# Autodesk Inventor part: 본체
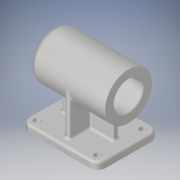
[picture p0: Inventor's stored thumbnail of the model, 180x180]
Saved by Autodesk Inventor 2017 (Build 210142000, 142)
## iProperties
Part Number: 본체
Material: 알루미늄 6061
Document SubType Name: Modeling
Designer: 7-1
Density: 2.7 g/cm^3
Appearance: 알루미늄 - 평지
Mass: 1024.73 g
Surface Area: 758.632 cm^2
Volume: 379.531 cm^3
Author: 7-1
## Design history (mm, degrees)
sketch "스케치1"
  geometry: L1 (0, 0)-(-112, 0); L2 (0, 21)-(0, 34); L3 (-112, 0)-(-112, 24); L4 (-102, 34)-(0, 34); L5 (-106, 0)-(-106, 10.5); L6 (-106, 10.5)-(-103, 10.5); L7 (-103, 10.5)-(-103, 15.7); L8 (-102.7, 16)-(-99, 16); L9 (-99, 16)-(-99, 17.2); L10 (-98.7, 17.5)-(-81, 17.5); L11 (-69, 24)-(-15, 24); L12 (-15, 24)-(-15, 21); L13 (-69, 24)-(-69, 21); L14 (-69, 21)-(-80.7, 21); L15 (-81, 20.7)-(-81, 17.5); L16 (-15, 21)-(0, 21); L17 (0, 34)-(0, 0); L18 (-112, 0)-(-106, 0); L19 (0, 34)-(0, 21); A1 r 0.3 centre (-102.7, 15.7) between (-102.7, 16) and (-103, 15.7); A2 r 0.3 centre (-98.7, 17.2) between (-98.7, 17.5) and (-99, 17.2); A3 r 0.3 centre (-80.7, 20.7) between (-80.7, 21) and (-81, 20.7); A4 r 10 centre (-102, 24) between (-102, 34) and (-112, 24)
  constraints: 38 end point, 13 perpendicular, 8 point on circle, 8 tangent, 4 centre point, 3 vertical, 2 equal radius, 1 collinear, 1 horizontal, 1 point on line
  dimensions: "d1" = 112 distance between parallel lines of L2 L3; "d2" = 21 diameter of L6 L1; "d3" = 32 diameter of L8 L1; "d4" = 35 diameter of L10 L1; "d5" = 42 diameter of L14 L1; "d6" = 48 diameter of L11 L1; "d7" = 68 diameter of L4 L1; "d8" = 42 diameter of L16 L1; "d9" = 15 distance between parallel lines of L2 L12; "d10" = 54 distance between parallel lines of L12 L13; "d11" = 12 distance between parallel lines of L13 L15; "d12" = 18 distance between parallel lines of L15 L9; "d13" = 3 distance between parallel lines of L7 L5; "d14" = 4 distance between parallel lines of L9 L7; "d15" = 0.3 radius of A1; "d16" = 10 radius of A4
revolve "회전1" sketch "스케치1" stored, may be unused: angle "d17" = 90 deg
node "스케치2"
node "작업 평면1"
sketch "스케치3"
  geometry: L1 (100, -45)-(12, -45); L2 (0, -33)-(0, 33); L3 (12, 45)-(100, 45); L4 (112, 33)-(112, -33); A1 r 12 centre (100, -33) between (100, -45) and (112, -33); A2 r 12 centre (100, 33) between (112, 33) and (100, 45); A3 r 12 centre (12, 33) between (12, 45) and (0, 33); A4 r 12 centre (12, -33) between (0, -33) and (12, -45); 4 further points
  constraints: 8 end point, 8 point on circle, 8 tangent, 6 point on line, 4 centre point, 3 equal radius, 2 parallel, 1 horizontal, 1 perpendicular
  dimensions: "d19" = 112 distance of point (0, 45) point (112, 45); "d20" = 90 distance of point (0, -45) point (0, 45); "d21" = 0 distance from line of point (0, 0) L2; "d22" = 45 distance from line of point (0, 0) L3; "d23" = 12 radius of A1
extrude "돌출1" join sketch "스케치3" distance "d24" = 10; taper "d25" = 0 deg
sketch "스케치4"
  geometry: A1 r 12 centre (-100, 33) between (-100, 45) and (-112, 33) reference; A2 r 12 centre (-100, -33) between (-112, -33) and (-100, -45) reference; A3 r 12 centre (-12, -33) between (-12, -45) and (0, -33) reference; A4 r 12 centre (-12, 33) between (0, 33) and (-12, 45) reference; 5 further points
  constraints: 4 coincident
hole "구멍1" sketch "스케치4" at (-100, -33), (-12, -33), (-100, 33), (-12, 33) diameter "d26" = 5.5; stored, may be unused: countersink angle "d30" = 82 deg, drill point angle "d32" = 0 deg; dims "d27" = 6, "d28" = 9.5, "d29" = 5.4, "d31" = 10
sketch "스케치5"
  geometry: L1 (-112, -33)-(-112, 33) reference; L2 (-94, 4)-(-94, 0); L3 (-18, 4)-(-18, 0); L4 (-12, -45)-(-100, -45) reference; L5 (0, 0)-(-112, 0); L6 (-56, 0)-(-56, 34); L7 (-60, 4)-(-60, 34); L8 (-52, 4)-(-52, 34); L9 (-60, 34)-(-52, 34); L10 (-18, 4)-(-52, 4); L11 (-60, 4)-(-94, 4); L12 (0, 33)-(0, -33) reference; L13 (-52, -4)-(-52, -34); L14 (-60, -34)-(-52, -34); L15 (-60, -4)-(-60, -34); L16 (-60, -4)-(-94, -4); L17 (-94, -4)-(-94, 0); L18 (-18, -4)-(-52, -4); L19 (-18, -4)-(-18, 0)
  constraints: 32 end point, 6 symmetric about line, 3 vertical, 2 midpoint, 2 parallel, 1 horizontal, 1 point on line
  dimensions: "d42" = 76 distance of L3.start L2.start; "d43" = 76 distance of L3.end L2.end; "d47" = 4 distance between parallel lines of L6 L7; "d48" = 4 distance between parallel lines of L6 L8; "d49" = 68 diameter of L9 L5; "d50" = 8 diameter of L10 L5; "d53" = 8 diameter of L11 L5; "d54" = 94 distance between parallel lines of L12 L2
extrude "돌출2" join sketch "스케치5" stored distance "d55" = 10; taper "d56" = 0 deg
sketch "스케치6" dims "d57" = 52
  geometry: 6 further points
  constraints: 2 vertical alignment, 1 coincident, 7 other
  dimensions: "d60" = 360 deg dimension on point (0, 0) point (0, 26) (derived)
hole "구멍2" sketch "스케치6" at (0, -26), (-26, 0), (0, 26), (26, 0) diameter "d62" = 3.242; stored, may be unused: countersink angle "d66" = 90 deg, drill point angle "d68" = 118 deg; dims "d63" = 8, "d64" = 4, "d65" = 2, "d67" = 11
sketch "스케치7"
  geometry: L1 (100, 0)-(100, 10) reference; 2 further points
  constraints: 1 other
  dimensions: "d69" = 56 distance from line of L1 point (44, 3); "d70" = 3 vertical distance of L1.start point (44, 3)
feature "엠보싱1" sketch "스케치7" dims "d1" = 112, "d2" = 21, "d3" = 32, "d4" = 35, "d5" = 42, "d6" = 48, "d7" = 68, "d8" = 42, "d9" = 15, "d10" = 54, "d11" = 12, "d12" = 18, "d13" = 3, "d14" = 4, "d15" = 0.3, "d16" = 10, "d71" = 0.5, "d72" = 0
fillet "모깎기1" dims "d73" = 3
fillet "모깎기2" dims "d74" = 3
fillet "모깎기3" dims "d75" = 3
chamfer "모따기1" distance "d76" = 1; stored, may be unused: second distance "d77" = 2, angle "d78" = 45 deg
fillet "모깎기5" dims "d80" = 3
fillet "모깎기6" dims "d81" = 3
node "솔리드1"
other parameters: "d18" = -74
